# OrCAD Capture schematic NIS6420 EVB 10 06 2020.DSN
size C
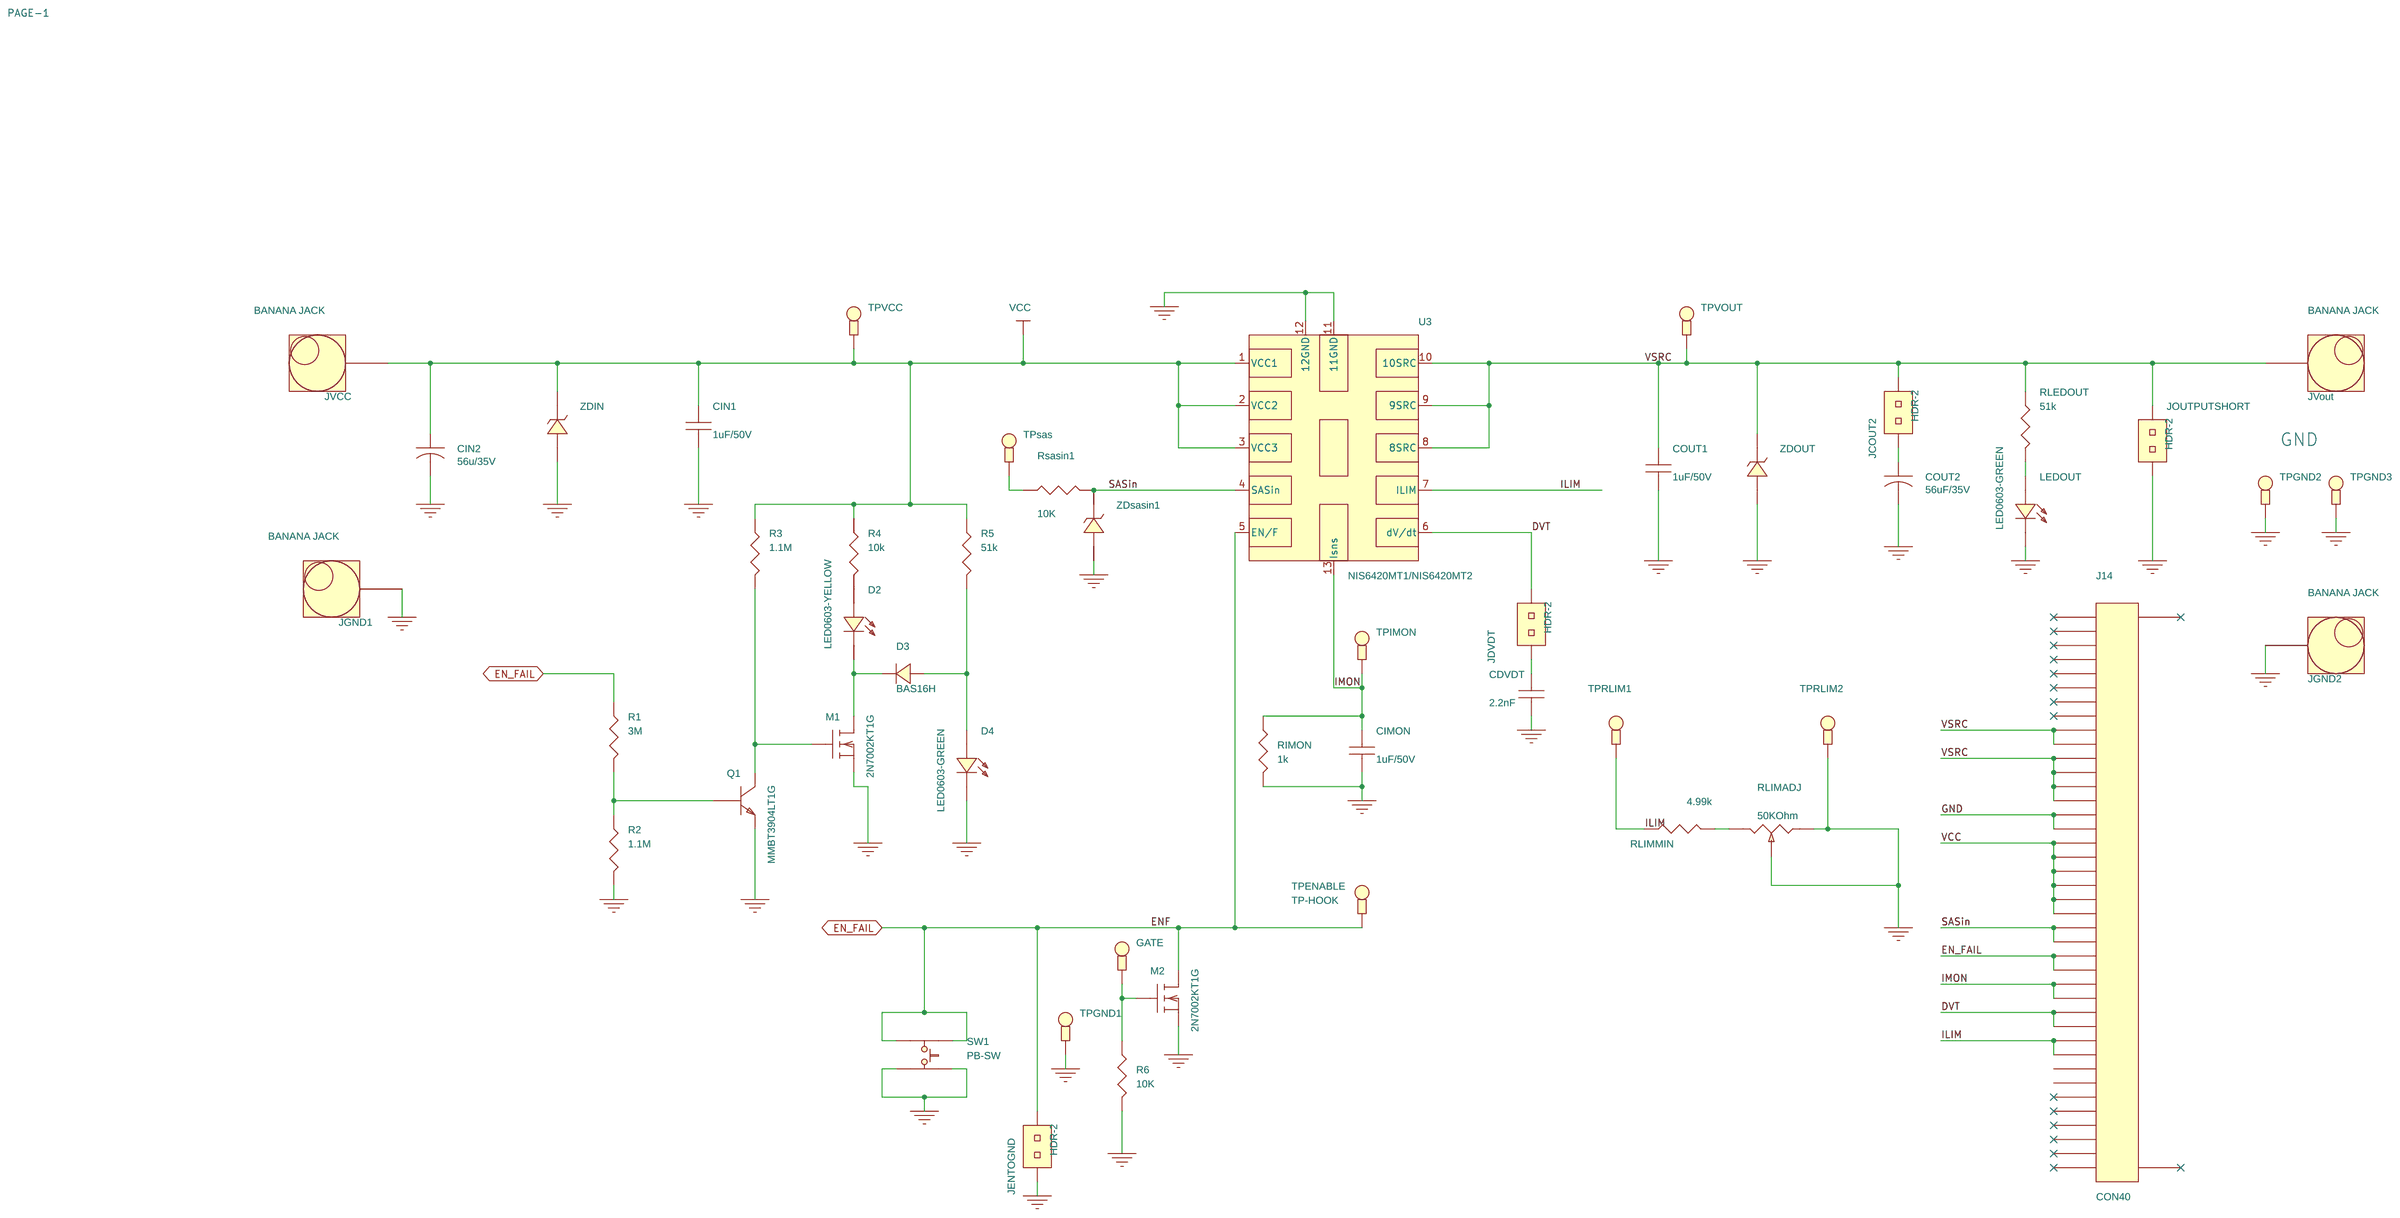
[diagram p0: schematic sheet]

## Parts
CDVDT  2.2nF  [C0805]
CIMON  1uF/50V  [0603]
CIN1  1uF/50V  [0805]
CIN2  56u/35V  [cap_smd_8p3x8p3]
COUT1  1uF/50V  [0805]
COUT2  56uF/35V  [cap_smd_8p3x8p3]
D2  LED0603-YELLOW  [LED0603]
D3  BAS16H  [SOD-323]
D4  LED0603-GREEN  [LED0603]
GATE  TP-HOOK  [TP-HOOK]
J14  CON40  [abc20drt]
JCOUT2  HDR-2  [HEADER-2]
JDVDT  HDR-2  [HEADER-2]
JENTOGND  HDR-2  [HEADER-2]
JGND1  BANANA JACK  [banana_via]
JGND2  BANANA JACK  [banana_via]
JOUTPUTSHORT  HDR-2  [HEADER-2]
JVCC  BANANA JACK  [banana_via]
JVout  BANANA JACK  [banana_via]
LEDOUT  LED0603-GREEN  [LED0603]
M1  2N7002KT1G  [SOT-23]
M2  2N7002KT1G  [SOT-23]
Q1  MMBT3904LT1G  [SOT-23]
R1  3M  [0603]
R2  1.1M  [0603]
R3  1.1M  [0603]
R4  10k  [0603]
R5  51k  [0603]
R6  10K  [0603]
RIMON  1k  [0603]
RLEDOUT  51k  [0603]
RLIMADJ  50KOhm  [3214x_trim_pot]
RLIMMIN  4.99k  [0805]
Rsasin1  10K  [0603]
SW1  PB-SW  [SW-TAC-SPST]
TPENABLE  TP-HOOK  [TP-HOOK]
TPGND1  TP-HOOK  [TP-HOOK]
TPGND2  TP-HOOK  [TP-HOOK]
TPGND3  TP-HOOK  [TP-HOOK]
TPIMON  TP-HOOK  [TP-HOOK]
TPRLIM1  TP-HOOK  [TP-HOOK]
TPRLIM2  TP-HOOK  [TP-HOOK]
TPsas  TP-HOOK  [TP-HOOK]
TPVCC  TP-HOOK  [TP-HOOK]
TPVOUT  TP-HOOK  [TP-HOOK]
U3  NIS6420MT1/NIS6420MT2  [NIS6452]
ZDIN  ZDIN  [0805]
ZDOUT  DIODE ZENER  [0805]
ZDsasin1  DIODE ZENER 5.1V  [0805]

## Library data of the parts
CDVDT = CAP_NP: CAP CER 0.1UF 50V 20% Z5U 0805; DIGIKEY: 399-1176-1-ND; Manufacturer: Kemet; Manufacturer Part #: C0805C104M5UACTU; Price: 0.065
CIMON CIN1 COUT1 = CAP_NP: CAP CER 0.1UF 50V 10% X7R 0603; DIGIKEY: 399-5089-1-ND; Manufacturer: Kemet; Manufacturer Part #: C0603C104K5RACTU; Price: 0.10000
CIN2 COUT2 = CAP: CAP ALUM POLY 56UF 20% 35V SMD; DIGIKEY: P121400CT-ND; Manufacturer: Panasonic Electronic Components; Manufacturer Part #: EEH-ZK1V560P; Price: 1.8000
D2 LEDOUT = LED_0: LED YELLOW CLEAR THIN 0603 SMD; DIGIKEY: 160-1448-1-ND; Manufacturer: Lite-On Inc; Manufacturer Part #: LTST-C191KSKT; Price: 0.248
D3 = DIODE_0: DIODE SWITCHING 100V 0.2A SOD323; DIGIKEY: BAS16HT1GOSCT-ND; Manufacturer: ON Semiconductor; Manufacturer Part #: BAS16HT1G; Price: 0.20
D4 = LED_0: LED GREEN CLEAR 0603 SMD; DIGIKEY: 160-1888-1-ND; Manufacturer: Lite-On Inc; Manufacturer Part #: LTST-C191TGKT; Price: 0.394
GATE TPIMON TPRLIM1 TPRLIM2 TPVCC TPVOUT = TP-HOOK: TEST POINT PC MINI .040"D RED; DIGIKEY: 5000K-ND; Manufacturer: Keystone Electronics; Manufacturer Part #: 5000; Price: 0.34000
J14 = CON40_0: CONN EDGE DUAL FMALE 40POS 0.100; DIGIKEY: S3314-ND; Manufacturer: Sullins Connector Solutions; Manufacturer Part #: EBC20DRTH; Price: 5.05
JCOUT2 JDVDT JENTOGND JOUTPUTSHORT = HEADER_2_1: CONN HEADER VERT SGL 2POS GOLD; DIGIKEY: 3M9447-ND; Manufacturer: 3M; Manufacturer Part #: 961102-6404-AR; Price: 0.16000
JGND1 JGND2 JVCC JVout = Banana_Conn: JACK NON-INSULATED .350"; DIGIKEY: 36-575-8-ND; Manufacturer: Keystone Electronics; Manufacturer Part #: 575-8; Manufacturer Part#: 575-8; Price: 0.99
M1 M2 = MMDF4N01HD_ON_1: MOSFET N-CH 60V 320MA SOT-23; DIGIKEY: 2N7002KT1GOSCT-ND; Manufacturer: ON Semiconductor; Price: 0.23000
Q1 = MMBT3904_SOT: TRANS NPN 40V 200MA SOT23; DIGIKEY: MMBT3904LT1GOSCT-ND; Manufacturer: ON Semiconductor; Price: 0.12000
R1 = RESISTOR: RES 3M OHM 1/10W 5% 0603 SMD; DIGIKEY: P3.0MGCT-ND; Manufacturer: Panasonic Electronic Components; Manufacturer Part #: ERJ-3GEYJ305V; Price: 0.0126
R2 = RESISTOR: RES 1.1M OHM 1/10W 5% 0603 SMD; DIGIKEY: P1.1MGCT-ND; Manufacturer: Panasonic Electronic Components; Manufacturer Part #: ERJ-3GEYJ115V; Price: 0.0126
R3 = RESISTOR: RES 1M OHM 1/10W 5% 0603 SMD; DIGIKEY: P1.0MGCT-ND; Manufacturer: Panasonic Electronic Components; Manufacturer Part #: ERJ-3GEYJ105V; Price: 0.0126
R4 R5 = RESISTOR: RES 1K OHM 1/10W 5% 0603 SMD; DIGIKEY: P2.49KDBCT-ND; Manufacturer: Panasonic Electronic Components; Manufacturer Part #: ERA-3AEB2491V; Price: 0.25
R6 RIMON = RESISTOR: RES 10K OHM 1/10W 5% 0603 SMD; DIGIKEY: P10KGCT-ND; Manufacturer: Panasonic Electronic Components; Manufacturer Part #: ERJ-3GEYJ103V; Price: 0.10000
RLEDOUT = RESISTOR: RES 680 OHM 1/10W 5% 0603 SMD; DIGIKEY: P680GCT-ND; Manufacturer: Panasonic Electronic Components; Manufacturer Part #: ERJ-3GEYJ681V; Price: 0.01260
RLIMADJ = POT_SM: TRIMMER 100 OHM 0.25W GW TOP ADJ; DIGIKEY: 3214X-1-101ECT-ND; Manufacturer: Bourns Inc.; Manufacturer Part #: 3214X-1-101E; Manufacturer part#: PV36W201C01B00; Price: 3.24; Supplier: www.digikey.com; Supplier part#: 3214X-1-101ECT-ND
RLIMMIN = RESISTOR: RES 20 OHM 1% 1/4W 0805; DIGIKEY: RNCP0805FTD20R0CT-ND; Manufacturer: Stackpole Electronics Inc.; Manufacturer Part #: RNCP0805FTD20R0; Price: 0.10
Rsasin1 = RESISTOR: RES 680 OHM 1/10W 5% 0603 SMD; DIGIKEY: P680GCT-ND; Manufacturer: StackpoleElectronicsIncomponents; Manufacturer Part #: RNCP0603FTD10K0; Price: 0.1
SW1 = PUSH-BUTTON-SW_0: SWITCH TACTILE SPST-NO 0.05A 12V; DIGIKEY: EG4369-ND; Manufacturer: E-Switch; Manufacturer Part #: TL1105FF160Q; Price: 0.19000
TPENABLE = TP-HOOK: TEST POINT PC MINI .040"D YELLOW; DIGIKEY: 5004K-ND; Manufacturer: Keystone Electronics; Manufacturer Part #: 5004; Price: 0.34000
TPGND1-TPGND3 TPsas = TP-HOOK: TEST POINT PC MINI .040"D BLACK; DIGIKEY: 5001K-ND; Manufacturer: Keystone Electronics; Manufacturer Part #: 5001; Price: 0.34000
U3 = NIS6452
ZDIN ZDOUT = DIODE_ZENER: DIODE ZENER 33V 500MW SOD123; DIGIKEY: MMSZ5257BT1GOSCT-ND; Manufacturer: ON Semiconductor; Manufacturer Part #: MMSZ5257BT1G; Price: 0.25
ZDsasin1 = DIODE_ZENER: DIODE ZENER 33V 500MW SOD123; DIGIKEY: MMSZ5257BT1GOSCT-ND; Manufacturer: ON Semiconductor; Manufacturer Part #: MMSZ4679T1G; Price: 0.25

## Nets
GND: CDVDT.2 CIMON.2 CIN1.2 CIN2.2 COUT1.2 COUT2.2 D4.1(CATHODE) J14.15 J14.16 JENTOGND.2 JGND1.1 JGND2.1 JOUTPUTSHORT.2 LEDOUT.1(CATHODE) M1.2(S) M2.2(S) Q1.2(E) R2.2 R6.2 RIMON.2 RLIMADJ.1(A) RLIMADJ.2(WIPER) SW1.1 SW1.2 TPGND1.1 TPGND2.1 TPGND3.1 TPRLIM2.1 U3.11(11GND) U3.12(12GND) ZDIN.2(ANODE) ZDOUT.2(ANODE) ZDsasin1.2(ANODE)
VCC: CIN1.1 CIN2.1 J14.17 J14.18 J14.19 J14.20 J14.21 J14.22 JVCC.1 R3.1 R4.1 R5.1 TPVCC.1 U3.1(VCC1) U3.2(VCC2) U3.3(VCC3) ZDIN.1(CATHODE)
DVT: J14.29 J14.30 JDVDT.1 U3.6(dV/dt)
EN_FAIL: J14.25 J14.26 JENTOGND.1 M2.3(D) R1.1 SW1.3 SW1.4 TPENABLE.1 U3.5(EN/F)
ILIM: J14.31 J14.32 RLIMMIN.2 TPRLIM1.1 U3.7(ILIM)
IMON: CIMON.1 J14.27 J14.28 RIMON.1 TPIMON.1 U3.13(Isns)
SASin: J14.23 J14.24 Rsasin1.2 U3.4(SASin) ZDsasin1.1(CATHODE)
VSRC: COUT1.1 J14.9 J14.10 J14.11 J14.12 J14.13 J14.14 JCOUT2.1 JOUTPUTSHORT.1 JVout.1 RLEDOUT.1 TPVOUT.1 U3.8(8SRC) U3.9(9SRC) U3.10(10SRC) ZDOUT.1(CATHODE)
N12391538: LEDOUT.2(ANODE) RLEDOUT.2
N12391596: GATE.1 M2.1(G) R6.1
N12393096: RLIMADJ.3(B) RLIMMIN.1
N14398226: M1.1(G) Q1.3(C) R3.2
N14398234: D3.1(A) D4.2(ANODE) R5.2
N14398270: D2.1(CATHODE) D3.2(K) M1.3(D)
N14398290: Q1.1(B) R1.2 R2.1
N14404692: COUT2.1 JCOUT2.2
N14424104: CDVDT.1 JDVDT.2
N14438244: Rsasin1.1 TPsas.1
N14457295: D2.2(ANODE) R4.2

Not connected (* = marked no-connect by the designer): J14 1* 2* 3* 4* 5* 6* 7* 8* 33 34 35* 36* 37* 38* 39* 40* 41* 42*

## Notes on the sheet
- PAGE-1
- GND
